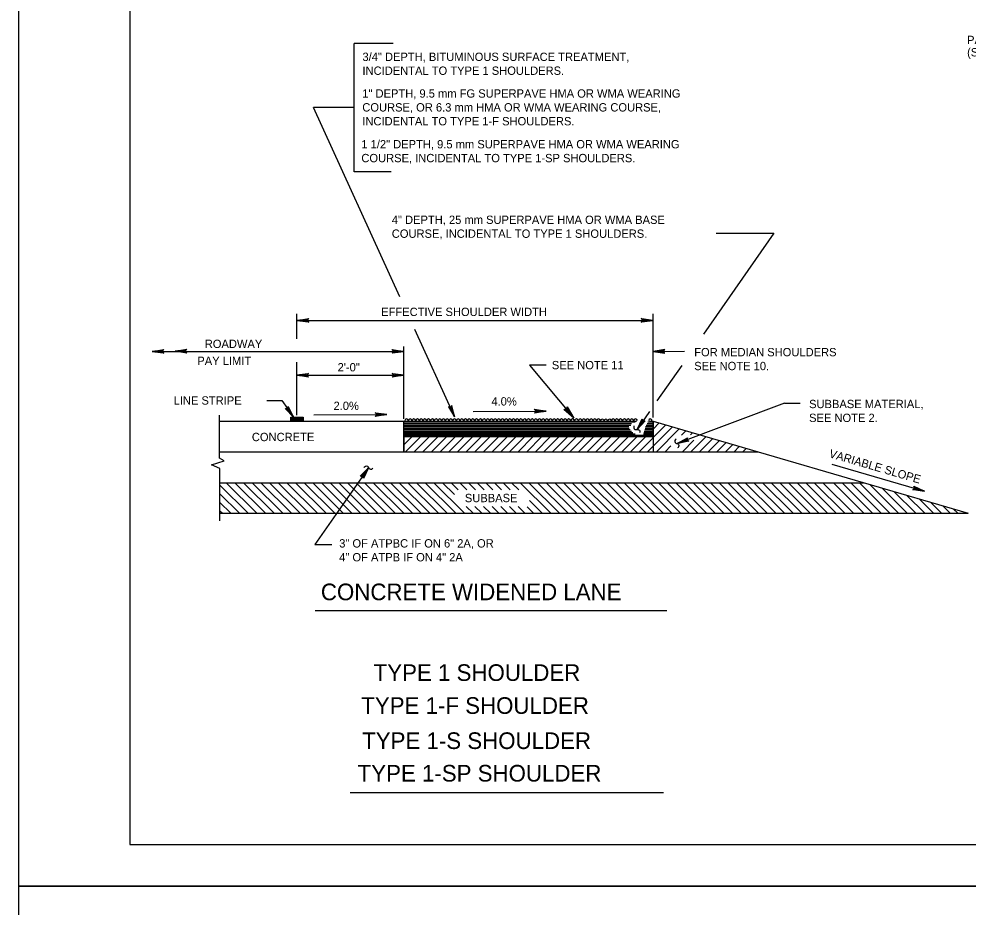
# Model space of a CAD drawing. Extents: x 638216 to 639962, y 297510 to 299292.
# Drawn here: x 638215.9 to 638558.2, y 298690.7 to 299010.9 of the extents above; entities that cross this region are included whole.
import ezdxf

# ---------------------------------------------------------------- set-up
doc = ezdxf.new("R2010")
doc.units = 0
for name, color, linetype in [('1', 7, 'Continuous'), ('2', 7, 'Continuous'), ('3', 7, 'Continuous'), ('PLT-BNDY', 7, 'Continuous')]:
    doc.layers.add(name, color=color, linetype=linetype)

msp = doc.modelspace()

# ---------------------------------------------------------------- linework, layer by layer
at = {"layer": '1'}
for p, q in [((638405.87, 298886.11), (638399.8, 298886.11)), ((638399.8, 298886.11), (638415.85, 298866.98))]:
    msp.add_line(p, q, dxfattribs=at)
for points in [[(639041.88, 298713.24), (639041.88, 299277.24), (638255.88, 299277.24), (638255.88, 298713.24), (639041.88, 298713.24), (639041.88, 298739.6), (638841.88, 298739.6), (638841.88, 298804.28), (639041.88, 298804.28), (639041.88, 298833.24), (638841.88, 298833.24), (638841.88, 298713.24), (638920.69, 298713.24), (638920.69, 298739.6), (638920.69, 298713.24), (638997.69, 298713.24), (638997.69, 298739.6), (638997.69, 298727.28), (639041.88, 298727.28)], [(638413.35, 298870.82), (638413.2, 298870.47), (638415.85, 298866.98), (638413.35, 298870.82), (638413.35, 298871.12), (638415.85, 298866.98), (638412.86, 298870.18), (638412.51, 298870.09), (638415.85, 298866.98), (638412.18, 298870.13), (638412.51, 298870.09)]]:
    msp.add_lwpolyline(points, dxfattribs=at)
at = {"layer": '2'}
for p, q in [((638336.64, 298955.83), (638336.64, 299002.12)), ((638350.71, 299002.12), (638336.64, 299002.12)), ((638353.14, 298910.69), (638322.04, 298978.97)), ((638336.64, 298978.97), (638322.04, 298978.97)), ((638350.03, 298955.83), (638336.64, 298955.83)), ((638487.92, 298933.74), (638462.5, 298897.24)), ((638467.09, 298933.74), (638487.92, 298933.74)), ((638316.03, 298895.64), (638316.03, 298904.64)), ((638444.34, 298867.25), (638444.34, 298904.57)), ((638316.06, 298902.24), (638444.33, 298902.24)), ((638372.28, 298868.66), (638358.49, 298898.93)), ((638265.04, 298891.06), (638354.52, 298891.06)), ((638354.61, 298866.76), (638354.61, 298892.86)), ((638444.36, 298891.06), (638455.66, 298891.13)), ((638316.03, 298868.02), (638316.03, 298887.16)), ((638454.67, 298885.98), (638445.75, 298873.19)), ((638316.01, 298882.46), (638354.57, 298882.46)), ((638305.15, 298873.36), (638310.57, 298873.36)), ((638310.57, 298873.36), (638314.64, 298867.59)), ((638379.5, 298869.36), (638405.81, 298869.53)), ((638443.13, 298869.43), (638438.61, 298862.94)), ((638491.67, 298872.38), (638453.03, 298857.83)), ((638491.67, 298872.38), (638497.36, 298872.38)), ((638288.13, 298852.57), (638288.13, 298868.01)), ((638288.3, 298865.9), (638438.36, 298865.9)), ((638322.14, 298868.13), (638348.45, 298868.3)), ((638354.57, 298854.88), (638354.57, 298865.9)), ((638443.02, 298865.9), (638444.37, 298865.9)), ((638444.37, 298860.39), (638444.37, 298865.9)), ((638444.37, 298865.9), (638557.88, 298832.68)), ((638444.37, 298865.9), (638444.37, 298860.39)), ((638354.57, 298860.39), (638444.37, 298860.39)), ((638444.37, 298860.39), (638354.57, 298860.39)), ((638354.57, 298860.39), (638354.57, 298854.88)), ((638444.37, 298860.39), (638444.37, 298854.85)), ((638288.13, 298854.85), (638482.13, 298854.85)), ((638341.8, 298849.12), (638322.49, 298821.38)), ((638508.72, 298850.45), (638542.2, 298840.61)), ((638288.13, 298843.7), (638520.24, 298843.7)), ((638372.77, 298839.41), (638368.48, 298843.7)), ((638374.11, 298841.19), (638371.59, 298843.7)), ((638377.24, 298841.17), (638374.71, 298843.7)), ((638380.36, 298841.17), (638377.83, 298843.7)), ((638383.47, 298841.17), (638380.94, 298843.7)), ((638386.59, 298841.17), (638384.06, 298843.7)), ((638389.7, 298841.17), (638387.17, 298843.7)), ((638392.82, 298841.17), (638390.29, 298843.7)), ((638395.94, 298841.17), (638393.41, 298843.7)), ((638379.49, 298832.68), (638377, 298835.17)), ((638382.61, 298832.68), (638380.12, 298835.17)), ((638385.73, 298832.68), (638383.24, 298835.17)), ((638388.84, 298832.68), (638386.35, 298835.17)), ((638391.96, 298832.68), (638389.47, 298835.17)), ((638395.08, 298832.68), (638392.58, 298835.17)), ((638398.19, 298832.68), (638395.7, 298835.17)), ((638401.31, 298832.68), (638398.98, 298835.01)), ((638404.42, 298832.68), (638399.81, 298837.29)), ((638288.3, 298832.68), (638557.88, 298832.68)), ((638288.3, 298832.68), (638504.3, 298832.68)), ((638322.49, 298821.38), (638328.62, 298821.38)), ((638322.61, 298797.7), (638449.32, 298797.7)), ((638335.26, 298732.04), (638448.15, 298732.04))]:
    msp.add_line(p, q, dxfattribs=at)
for points in [[(638320.07, 298901.74), (638319.92, 298902.03), (638316.06, 298902.24), (638320.07, 298901.74), (638320.27, 298901.57), (638316.06, 298902.24), (638319.91, 298902.43), (638320.05, 298902.72), (638316.06, 298902.24), (638320.27, 298902.91), (638320.05, 298902.72)], [(638440.32, 298902.75), (638440.47, 298902.46), (638444.33, 298902.24), (638440.32, 298902.75), (638440.12, 298902.92), (638444.33, 298902.24), (638440.48, 298902.05), (638440.33, 298901.77), (638444.33, 298902.24), (638440.12, 298901.57), (638440.33, 298901.77)], [(638267.84, 298890.57), (638267.69, 298890.86), (638263.84, 298891.07), (638267.84, 298890.57), (638268.05, 298890.39), (638263.84, 298891.07), (638267.69, 298891.26), (638267.83, 298891.55), (638263.84, 298891.07), (638268.05, 298891.74), (638267.83, 298891.55)], [(638267.87, 298890.55), (638267.72, 298890.84), (638263.87, 298891.06), (638267.87, 298890.55), (638268.08, 298890.38), (638263.87, 298891.06), (638267.72, 298891.25), (638267.86, 298891.53), (638263.87, 298891.06), (638268.08, 298891.73), (638267.86, 298891.53)], [(638276.17, 298890.64), (638276.02, 298890.93), (638272.17, 298891.15), (638276.17, 298890.64), (638276.38, 298890.47), (638272.17, 298891.15), (638276.02, 298891.34), (638276.16, 298891.63), (638272.17, 298891.15), (638276.38, 298891.82), (638276.16, 298891.63)], [(638350.52, 298891.56), (638350.67, 298891.27), (638354.52, 298891.06), (638350.52, 298891.56), (638350.32, 298891.73), (638354.52, 298891.06), (638350.67, 298890.87), (638350.53, 298890.58), (638354.52, 298891.06), (638350.32, 298890.39), (638350.53, 298890.58)], [(638448.36, 298891.56), (638448.21, 298891.27), (638444.36, 298891.06), (638448.36, 298891.56), (638448.57, 298891.73), (638444.36, 298891.06), (638448.21, 298890.87), (638448.35, 298890.58), (638444.36, 298891.06), (638448.57, 298890.39), (638448.35, 298890.58)], [(638320.01, 298881.95), (638319.87, 298882.24), (638316.01, 298882.46), (638320.01, 298881.95), (638320.22, 298881.78), (638316.01, 298882.46), (638319.86, 298882.65), (638320, 298882.93), (638316.01, 298882.46), (638320.22, 298883.13), (638320, 298882.93)], [(638350.57, 298882.96), (638350.72, 298882.67), (638354.57, 298882.46), (638350.57, 298882.96), (638350.36, 298883.13), (638354.57, 298882.46), (638350.72, 298882.27), (638350.58, 298881.98), (638354.57, 298882.46), (638350.36, 298881.79), (638350.58, 298881.98)], [(638312.84, 298870.95), (638312.69, 298870.66), (638314.74, 298867.39), (638312.84, 298870.95), (638312.87, 298871.22), (638314.74, 298867.39), (638312.36, 298870.43), (638312.05, 298870.38), (638314.74, 298867.39), (638311.77, 298870.44), (638312.05, 298870.38)], [(638370.83, 298870.93), (638371.15, 298870.91), (638372.84, 298867.44), (638370.83, 298870.93), (638370.59, 298871.06), (638372.84, 298867.44), (638371.53, 298871.06), (638371.74, 298871.3), (638372.84, 298867.44), (638371.83, 298871.58), (638371.74, 298871.3)], [(638401.8, 298870), (638401.95, 298869.72), (638405.81, 298869.53), (638401.8, 298870), (638401.59, 298870.18), (638405.81, 298869.53), (638401.96, 298869.31), (638401.82, 298869.03), (638405.81, 298869.53), (638401.6, 298868.83), (638401.82, 298869.03)], [(638313.79, 298867.24), (638313.94, 298867.39)], [(638313.79, 298866.2), (638314.98, 298867.39)], [(638313.79, 298866.51), (638314.66, 298867.39)], [(638313.79, 298866.82), (638314.35, 298867.39)], [(638313.79, 298867.13), (638314.04, 298867.39)], [(638313.88, 298865.98), (638315.29, 298867.39)], [(638314.19, 298865.98), (638315.6, 298867.39)], [(638314.5, 298865.98), (638315.91, 298867.39)], [(638314.81, 298865.98), (638316.22, 298867.39)], [(638315.12, 298865.98), (638316.53, 298867.39)], [(638315.43, 298865.98), (638316.84, 298867.39)], [(638315.75, 298865.98), (638317.16, 298867.39)], [(638316.06, 298865.98), (638317.47, 298867.39)], [(638316.37, 298865.98), (638317.78, 298867.39)], [(638316.68, 298865.98), (638318.09, 298867.39)], [(638316.99, 298865.98), (638318.31, 298867.29)], [(638317.3, 298865.98), (638318.31, 298866.98)], [(638317.62, 298865.98), (638318.31, 298866.67)], [(638317.93, 298865.98), (638318.31, 298866.36)], [(638318.14, 298865.98), (638318.31, 298866.15)], [(638318.24, 298865.98), (638318.31, 298866.05)], [(638344.44, 298868.78), (638344.59, 298868.49), (638348.45, 298868.3), (638344.44, 298868.78), (638344.23, 298868.95), (638348.45, 298868.3), (638344.6, 298868.09), (638344.46, 298867.8), (638348.45, 298868.3), (638344.24, 298867.6), (638344.46, 298867.8)], [(638354.57, 298865.84), (638354.63, 298865.9)], [(638441.31, 298865.93), (638440.99, 298865.97), (638438.61, 298862.94), (638441.31, 298865.93), (638441.57, 298866), (638438.61, 298862.94), (638440.66, 298866.2), (638440.5, 298866.48), (638438.61, 298862.94), (638440.47, 298866.77), (638440.5, 298866.48)], [(638354.57, 298865.61), (638437.86, 298865.61)], [(638354.57, 298865.06), (638436.58, 298865.06)], [(638354.57, 298864.51), (638436.32, 298864.51)], [(638354.57, 298863.96), (638435.61, 298863.96)], [(638354.57, 298863.41), (638435.71, 298863.41)], [(638354.57, 298862.86), (638436.08, 298862.86)], [(638439.3, 298854.85), (638448.99, 298864.54)], [(638441.36, 298862.86), (638444.37, 298862.86)], [(638441.52, 298863.41), (638444.37, 298863.41)], [(638441.69, 298863.96), (638444.37, 298863.96)], [(638441.89, 298864.51), (638444.37, 298864.51)], [(638442.22, 298865.06), (638444.37, 298865.06)], [(638442.41, 298854.85), (638451.39, 298863.83)], [(638442.48, 298865.61), (638444.37, 298865.61)], [(638444.37, 298863.04), (638446.58, 298865.25)], [(638445.56, 298854.88), (638453.8, 298863.12)], [(638454.66, 298860.87), (638456.2, 298862.41)], [(638354.57, 298862.31), (638436.58, 298862.31)], [(638354.57, 298861.76), (638437.1, 298861.76)], [(638354.57, 298861.29), (638437.89, 298861.29)], [(638354.57, 298860.84), (638444.37, 298860.84)], [(638354.57, 298857.37), (638357.59, 298860.39)], [(638355.2, 298854.88), (638360.7, 298860.39)], [(638358.31, 298854.88), (638363.82, 298860.39)], [(638361.43, 298854.88), (638366.94, 298860.39)], [(638364.54, 298854.88), (638370.05, 298860.39)], [(638367.66, 298854.88), (638373.17, 298860.39)], [(638370.78, 298854.88), (638376.28, 298860.39)], [(638373.89, 298854.88), (638379.4, 298860.39)], [(638377.01, 298854.88), (638382.52, 298860.39)], [(638380.13, 298854.88), (638385.63, 298860.39)], [(638383.24, 298854.88), (638388.75, 298860.39)], [(638386.36, 298854.88), (638391.87, 298860.39)], [(638389.47, 298854.88), (638394.98, 298860.39)], [(638392.59, 298854.88), (638398.1, 298860.39)], [(638395.71, 298854.88), (638401.21, 298860.39)], [(638398.82, 298854.88), (638404.33, 298860.39)], [(638401.94, 298854.88), (638407.45, 298860.39)], [(638405.05, 298854.88), (638410.56, 298860.39)], [(638408.17, 298854.88), (638413.68, 298860.39)], [(638411.29, 298854.88), (638416.79, 298860.39)], [(638414.4, 298854.88), (638419.91, 298860.39)], [(638417.52, 298854.88), (638423.03, 298860.39)], [(638420.63, 298854.88), (638426.14, 298860.39)], [(638423.75, 298854.88), (638429.26, 298860.39)], [(638426.83, 298854.85), (638432.37, 298860.39)], [(638429.95, 298854.85), (638435.49, 298860.39)], [(638433.1, 298854.88), (638438.61, 298860.39)], [(638436.18, 298854.85), (638441.72, 298860.39)], [(638440.88, 298861.29), (638444.37, 298861.29)], [(638441.02, 298861.76), (638444.37, 298861.76)], [(638441.19, 298862.31), (638444.37, 298862.31)], [(638456.95, 298858.78), (638456.71, 298858.99), (638453.03, 298857.83), (638456.95, 298858.78), (638457.21, 298858.68), (638453.03, 298857.83), (638456.57, 298859.37), (638456.6, 298859.69), (638453.03, 298857.83), (638456.73, 298859.94), (638456.6, 298859.69)], [(638454.91, 298854.88), (638459.06, 298859.03)], [(638457.9, 298860.99), (638458.61, 298861.69)], [(638458.03, 298854.88), (638463.42, 298860.27)], [(638461.14, 298854.88), (638465.82, 298859.56)], [(638448.68, 298854.88), (638450.8, 298857.01)], [(638464.26, 298854.88), (638468.23, 298858.85)], [(638467.38, 298854.88), (638470.63, 298858.14)], [(638470.49, 298854.88), (638473.04, 298857.43)], [(638473.61, 298854.88), (638475.44, 298856.72)], [(638476.72, 298854.88), (638477.85, 298856.01)], [(638288.3, 298848.82), (638285.28, 298850.13), (638289.86, 298851.66), (638288.13, 298852.57)], [(638288.3, 298829.93), (638288.3, 298848.82)], [(638339.13, 298846.1), (638339.45, 298846.06), (638341.8, 298849.12), (638339.13, 298846.1), (638338.86, 298846.03), (638341.8, 298849.12), (638339.78, 298845.84), (638339.94, 298845.56), (638341.8, 298849.12), (638339.97, 298845.27), (638339.94, 298845.56)], [(638298.48, 298832.68), (638288.3, 298842.86)], [(638301.59, 298832.68), (638290.57, 298843.7)], [(638304.71, 298832.68), (638293.69, 298843.7)], [(638307.82, 298832.68), (638296.81, 298843.7)], [(638310.94, 298832.68), (638299.92, 298843.7)], [(638314.06, 298832.68), (638303.04, 298843.7)], [(638317.17, 298832.68), (638306.15, 298843.7)], [(638320.29, 298832.68), (638309.27, 298843.7)], [(638323.4, 298832.68), (638312.39, 298843.7)], [(638326.52, 298832.68), (638315.5, 298843.7)], [(638329.64, 298832.68), (638318.62, 298843.7)], [(638332.75, 298832.68), (638321.73, 298843.7)], [(638335.87, 298832.68), (638324.85, 298843.7)], [(638338.99, 298832.68), (638327.97, 298843.7)], [(638342.1, 298832.68), (638331.08, 298843.7)], [(638345.22, 298832.68), (638334.2, 298843.7)], [(638348.33, 298832.68), (638337.32, 298843.7)], [(638351.45, 298832.68), (638340.43, 298843.7)], [(638354.57, 298832.68), (638343.55, 298843.7)], [(638357.68, 298832.68), (638346.66, 298843.7)], [(638360.8, 298832.68), (638349.78, 298843.7)], [(638363.91, 298832.68), (638352.9, 298843.7)], [(638367.03, 298832.68), (638356.01, 298843.7)], [(638370.15, 298832.68), (638359.13, 298843.7)], [(638373.26, 298832.68), (638362.24, 298843.7)], [(638376.38, 298832.68), (638365.36, 298843.7)], [(638407.54, 298832.68), (638396.52, 298843.7)], [(638410.66, 298832.68), (638399.64, 298843.7)], [(638413.77, 298832.68), (638402.75, 298843.7)], [(638416.89, 298832.68), (638405.87, 298843.7)], [(638420, 298832.68), (638408.99, 298843.7)], [(638423.12, 298832.68), (638412.1, 298843.7)], [(638426.24, 298832.68), (638415.22, 298843.7)], [(638429.35, 298832.68), (638418.34, 298843.7)], [(638432.47, 298832.68), (638421.45, 298843.7)], [(638435.58, 298832.68), (638424.57, 298843.7)], [(638438.7, 298832.68), (638427.68, 298843.7)], [(638441.82, 298832.68), (638430.8, 298843.7)], [(638444.93, 298832.68), (638433.92, 298843.7)], [(638448.05, 298832.68), (638437.03, 298843.7)], [(638451.17, 298832.68), (638440.15, 298843.7)], [(638454.28, 298832.68), (638443.26, 298843.7)], [(638457.4, 298832.68), (638446.38, 298843.7)], [(638460.51, 298832.68), (638449.5, 298843.7)], [(638463.63, 298832.68), (638452.61, 298843.7)], [(638466.75, 298832.68), (638455.73, 298843.7)], [(638469.86, 298832.68), (638458.85, 298843.7)], [(638472.98, 298832.68), (638461.96, 298843.7)], [(638476.09, 298832.68), (638465.08, 298843.7)], [(638479.21, 298832.68), (638468.19, 298843.7)], [(638482.33, 298832.68), (638471.31, 298843.7)], [(638485.44, 298832.68), (638474.43, 298843.7)], [(638488.56, 298832.68), (638477.54, 298843.7)], [(638491.67, 298832.68), (638480.66, 298843.7)], [(638494.79, 298832.68), (638483.77, 298843.7)], [(638497.91, 298832.68), (638486.89, 298843.7)], [(638501.02, 298832.68), (638490.01, 298843.7)], [(638504.14, 298832.68), (638493.12, 298843.7)], [(638507.26, 298832.68), (638496.24, 298843.7)], [(638510.37, 298832.68), (638499.36, 298843.7)], [(638513.49, 298832.68), (638502.47, 298843.7)], [(638516.6, 298832.68), (638505.59, 298843.7)], [(638520.36, 298832.68), (638509.34, 298843.7)], [(638523.48, 298832.68), (638512.46, 298843.7)], [(638526.59, 298832.68), (638515.57, 298843.7)], [(638529.71, 298832.68), (638518.69, 298843.7)], [(638532.83, 298832.68), (638522.46, 298843.05)], [(638538.5, 298842.22), (638538.56, 298841.9), (638542.2, 298840.61), (638538.5, 298842.22), (638538.35, 298842.45), (638542.2, 298840.61), (638538.45, 298841.51), (638538.23, 298841.28), (638542.2, 298840.61), (638537.97, 298841.15), (638538.23, 298841.28)], [(638295.36, 298832.68), (638288.3, 298839.74)], [(638535.94, 298832.68), (638526.86, 298841.76)], [(638539.06, 298832.68), (638531.27, 298840.47)], [(638542.3, 298832.68), (638535.86, 298839.13)], [(638292.24, 298832.68), (638288.3, 298836.62)], [(638545.46, 298832.68), (638540.32, 298837.82)], [(638548.35, 298832.68), (638544.41, 298836.62)], [(638551.42, 298832.68), (638548.75, 298835.35)], [(638289.13, 298832.68), (638288.3, 298833.51)], [(638554.14, 298832.68), (638552.6, 298834.23)]]:
    msp.add_lwpolyline(points, dxfattribs=at)
msp.add_lwpolyline([(638313.79, 298865.98), (638313.79, 298867.39), (638318.31, 298867.39), (638318.31, 298865.98)], close=True, dxfattribs=at)
for centre in [(638355.56, 298866.02), (638356.9, 298866.02), (638358.23, 298866.02), (638359.56, 298866.02), (638360.89, 298866.02), (638362.22, 298866.02), (638363.55, 298866.02), (638364.88, 298866.02), (638366.21, 298866.02), (638367.54, 298866.02), (638368.87, 298866.02), (638370.2, 298866.02), (638371.53, 298866.02), (638372.86, 298866.02), (638374.19, 298866.02), (638375.52, 298866.02), (638376.86, 298866.02), (638378.19, 298866.02), (638379.52, 298866.02), (638380.85, 298866.02), (638382.18, 298866.02), (638383.51, 298866.02), (638384.84, 298866.02), (638386.17, 298866.02), (638387.5, 298866.02), (638388.83, 298866.02), (638390.16, 298866.02), (638391.49, 298866.02), (638392.82, 298866.02), (638394.15, 298866.02), (638395.48, 298866.02), (638396.82, 298866.02), (638398.15, 298866.02), (638399.48, 298866.02), (638400.81, 298866.02), (638402.14, 298866.02), (638403.47, 298866.02), (638404.8, 298866.02), (638406.13, 298866.02), (638407.46, 298866.02), (638408.79, 298866.02), (638410.12, 298866.02), (638411.45, 298866.02), (638412.78, 298866.02), (638414.11, 298866.02), (638415.44, 298866.02), (638416.78, 298866.02), (638418.11, 298866.02), (638419.44, 298866.02), (638420.77, 298866.02), (638422.1, 298866.02), (638423.43, 298866.02), (638424.76, 298866.02), (638426.03, 298865.98), (638427.34, 298865.93), (638428.68, 298865.98), (638430.08, 298866.02), (638431.41, 298866.02), (638432.74, 298866.02), (638434.07, 298866.02), (638435.4, 298866.02), (638436.73, 298866.02), (638438.07, 298866.02), (638443.39, 298866.02)]:
    msp.add_arc(centre, 0.671, 10.6519, 178.7199, dxfattribs=at)
for points in [[(638437.48, 298864.28), (638437.4, 298863.87), (638437.56, 298863.14), (638438.13, 298862.85), (638438.61, 298862.94), (638439.17, 298862.84), (638439.59, 298862.37), (638439.62, 298862.12), (638439.52, 298861.73)], [(638452.72, 298859.56), (638452.44, 298859.25), (638452.22, 298858.54), (638452.58, 298858), (638453.03, 298857.83), (638453.47, 298857.48), (638453.59, 298856.86), (638453.5, 298856.63), (638453.21, 298856.33)], [(638340.12, 298849.19), (638340.41, 298849.5), (638341.1, 298849.79), (638341.66, 298849.49), (638341.88, 298849.06), (638342.28, 298848.66), (638342.9, 298848.59), (638343.12, 298848.71), (638343.39, 298849.03)]]:
    msp.add_spline(points, degree=3, dxfattribs=at)
at = {"layer": 'PLT-BNDY'}
for points in [[(638215.88, 299292.24), (639056.88, 299292.24), (639056.88, 298698.24), (638215.88, 298698.24)], [(638215.88, 298698.24), (639056.88, 298698.24), (639056.88, 298104.24), (638215.88, 298104.24)]]:
    msp.add_lwpolyline(points, close=True, dxfattribs=at)

# ---------------------------------------------------------------- texts
at = {"layer": '3'}
for s, height, p in [('PAY LIMIT FOR SY BINDER ITEM', 3, (638557.52, 299001.85)), ('(SEE NOTE 12)', 3, (638557.52, 298997.41)), ('3/4" DEPTH, BITUMINOUS SURFACE TREATMENT,', 3, (638339.65, 298995.77)), ('INCIDENTAL TO TYPE 1 SHOULDERS.', 3, (638339.65, 298990.77)), ('1" DEPTH, 9.5 mm FG SUPERPAVE HMA OR WMA WEARING', 3, (638339.59, 298982.55)), ('COURSE, OR 6.3 mm HMA OR WMA WEARING COURSE,', 3, (638339.59, 298977.55)), ('INCIDENTAL TO TYPE 1-F SHOULDERS.', 3, (638339.59, 298972.55)), ('1 1/2" DEPTH, 9.5 mm SUPERPAVE HMA OR WMA WEARING', 3, (638339.25, 298964.26)), ('COURSE, INCIDENTAL TO TYPE 1-SP SHOULDERS.', 3, (638339.25, 298959.26)), ('4" DEPTH, 25 mm SUPERPAVE HMA OR WMA BASE', 3, (638350.22, 298937.01)), ('COURSE, INCIDENTAL TO TYPE 1 SHOULDERS.', 3, (638350.22, 298932.01)), ('EFFECTIVE SHOULDER WIDTH', 3, (638346.39, 298903.82)), ('ROADWAY', 3, (638282.82, 298892.29)), ('FOR MEDIAN SHOULDERS', 3, (638459.2, 298889.29)), ('PAY LIMIT', 3, (638280.14, 298886.16)), ('2\'-0"', 3, (638330.69, 298883.85)), ('SEE NOTE 11', 3, (638407.89, 298884.62)), ('SEE NOTE 10.', 3, (638459.2, 298884.29)), ('LINE STRIPE', 3, (638271.6, 298871.86)), ('2.0%', 3, (638329.22, 298869.93)), ('4.0%', 3, (638386.11, 298871.54)), ('SUBBASE MATERIAL,', 3, (638500.58, 298870.6)), ('SEE NOTE 2.', 3, (638500.58, 298865.6)), ('CONCRETE', 3, (638299.79, 298858.7)), ('SUBBASE', 3, (638376.55, 298836.7)), ('3" OF ATPBC IF ON 6" 2A, OR', 3, (638331.27, 298820.35)), ('4" OF ATPB IF ON 4" 2A', 3, (638331.27, 298815.35)), ('CONCRETE WIDENED LANE', 6, (638324.66, 298801.35)), ('TYPE 1 SHOULDER', 6, (638343.68, 298772.25)), ('TYPE 1-F SHOULDER', 6, (638339.21, 298760.38)), ('TYPE 1-S SHOULDER', 6, (638339.53, 298747.71)), ('TYPE 1-SP SHOULDER', 6, (638337.91, 298735.97))]:
    msp.add_text(s, height=height, dxfattribs=at).set_placement(p)
msp.add_text('VARIABLE SLOPE', height=3, rotation=343.6873, dxfattribs=at).set_placement((638507.56, 298852.95))

doc.saveas('drawing.dxf')
